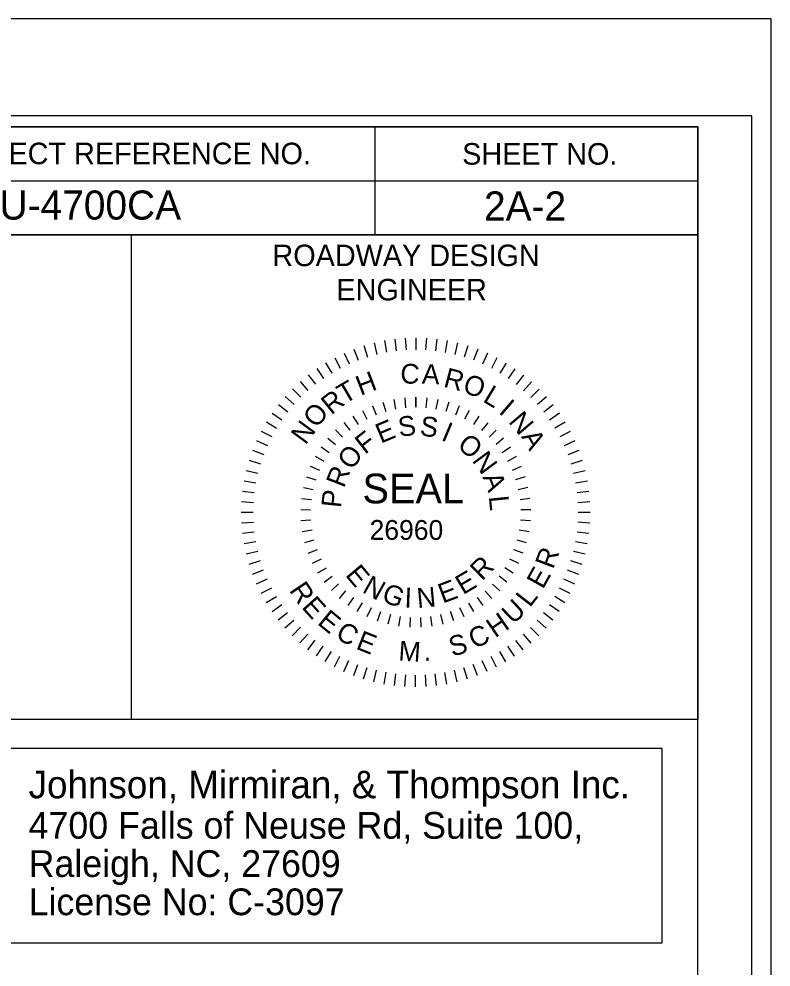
# Model space of a CAD drawing. Extents: x 2294370 to 2294957, y 719276 to 719941.
# Drawn here: x 2294757.04 to 2294791.96, y 719452.35 to 719496.34 of the extents above; entities that cross this region are included whole.
import ezdxf

# ---------------------------------------------------------------- set-up
doc = ezdxf.new("R2010")
doc.units = 0
for name, color, linetype in [('Default', 7, 'Continuous'), ('Old_Level_11', 7, 'Continuous'), ('Sheet Cutting Line CELL', 7, 'Continuous'), ('Sheet Data Field CELL', 7, 'Continuous'), ('Sheet Plan CELL', 7, 'Continuous'), ('Sheet Plot Border Inside CELL', 7, 'Continuous'), ('Sheet Plot Border Outside CELL', 7, 'Continuous'), ('Sheet Typical CELL', 7, 'Continuous')]:
    doc.layers.add(name, color=color, linetype=linetype)

msp = doc.modelspace()

# ---------------------------------------------------------------- linework, layer by layer
at = {"layer": 'Default'}
for p, q in [((2294774.009, 719481.414), (2294774.108, 719480.871)), ((2294774.493, 719481.487), (2294774.559, 719480.939)), ((2294774.98, 719481.531), (2294775.013, 719480.98)), ((2294775.47, 719481.545), (2294775.469, 719480.993)), ((2294775.959, 719481.53), (2294775.925, 719480.979)), ((2294776.446, 719481.485), (2294776.379, 719480.937)), ((2294776.93, 719481.412), (2294776.83, 719480.869)), ((2294772.597, 719481.022), (2294772.793, 719480.505)), ((2294773.059, 719481.181), (2294773.223, 719480.653)), ((2294773.531, 719481.312), (2294773.662, 719480.776)), ((2294777.407, 719481.308), (2294777.276, 719480.772)), ((2294777.88, 719481.177), (2294777.715, 719480.649)), ((2294778.341, 719481.017), (2294778.145, 719480.5)), ((2294771.705, 719480.621), (2294771.961, 719480.132)), ((2294772.145, 719480.834), (2294772.37, 719480.331)), ((2294778.793, 719480.828), (2294778.567, 719480.325)), ((2294779.233, 719480.614), (2294778.976, 719480.125)), ((2294770.867, 719480.116), (2294771.18, 719479.661)), ((2294771.278, 719480.381), (2294771.564, 719479.908)), ((2294779.659, 719480.373), (2294779.373, 719479.901)), ((2294780.07, 719480.107), (2294779.756, 719479.653)), ((2294770.473, 719479.826), (2294770.813, 719479.391)), ((2294780.463, 719479.817), (2294780.123, 719479.383)), ((2294770.096, 719479.513), (2294770.462, 719479.1)), ((2294780.839, 719479.503), (2294780.473, 719479.09)), ((2294769.404, 719478.822), (2294769.817, 719478.456)), ((2294769.74, 719479.178), (2294770.13, 719478.787)), ((2294774.951, 719478.759), (2294774.996, 719478.302)), ((2294775.467, 719478.784), (2294775.467, 719478.324)), ((2294775.467, 719478.324), (2294775.467, 719478.784)), ((2294775.983, 719478.758), (2294775.938, 719478.301)), ((2294781.195, 719479.167), (2294780.804, 719478.778)), ((2294781.53, 719478.811), (2294781.117, 719478.445)), ((2294769.09, 719478.446), (2294769.525, 719478.106)), ((2294773.453, 719478.392), (2294773.626, 719477.965)), ((2294773.941, 719478.563), (2294774.071, 719478.121)), ((2294774.441, 719478.685), (2294774.529, 719478.233)), ((2294776.492, 719478.683), (2294776.404, 719478.232)), ((2294776.993, 719478.56), (2294776.862, 719478.118)), ((2294777.48, 719478.388), (2294777.306, 719477.962)), ((2294781.843, 719478.434), (2294781.408, 719478.095)), ((2294768.8, 719478.053), (2294769.254, 719477.739)), ((2294772.54, 719477.914), (2294772.792, 719477.528)), ((2294772.986, 719478.174), (2294773.198, 719477.767)), ((2294777.947, 719478.17), (2294777.734, 719477.763)), ((2294778.392, 719477.908), (2294778.14, 719477.523)), ((2294782.133, 719478.041), (2294781.678, 719477.727)), ((2294768.534, 719477.642), (2294769.006, 719477.356)), ((2294772.123, 719477.611), (2294772.411, 719477.251)), ((2294778.809, 719477.604), (2294778.52, 719477.245)), ((2294782.398, 719477.63), (2294781.925, 719477.344)), ((2294768.293, 719477.216), (2294768.782, 719476.959)), ((2294771.737, 719477.269), (2294772.058, 719476.939)), ((2294779.195, 719477.262), (2294778.873, 719476.933)), ((2294782.638, 719477.203), (2294782.149, 719476.947)), ((2294768.079, 719476.776), (2294768.582, 719476.55)), ((2294771.385, 719476.892), (2294771.736, 719476.595)), ((2294779.546, 719476.884), (2294779.194, 719476.588)), ((2294782.851, 719476.762), (2294782.348, 719476.537)), ((2294767.891, 719476.324), (2294768.407, 719476.128)), ((2294771.071, 719476.482), (2294771.449, 719476.22)), ((2294779.859, 719476.474), (2294779.48, 719476.212)), ((2294783.039, 719476.31), (2294782.522, 719476.115)), ((2294767.731, 719475.863), (2294768.259, 719475.698)), ((2294770.799, 719476.045), (2294771.2, 719475.819)), ((2294780.13, 719476.036), (2294779.728, 719475.812)), ((2294783.198, 719475.848), (2294782.67, 719475.685)), ((2294767.599, 719475.39), (2294768.135, 719475.259)), ((2294770.569, 719475.582), (2294770.991, 719475.398)), ((2294780.359, 719475.573), (2294779.937, 719475.389)), ((2294783.329, 719475.376), (2294782.793, 719475.245)), ((2294767.496, 719474.913), (2294768.039, 719474.813)), ((2294770.387, 719475.099), (2294770.824, 719474.957)), ((2294780.541, 719475.09), (2294780.103, 719474.949)), ((2294783.431, 719474.898), (2294782.888, 719474.799)), ((2294767.422, 719474.429), (2294767.97, 719474.362)), ((2294770.25, 719474.602), (2294770.7, 719474.502)), ((2294780.676, 719474.592), (2294780.227, 719474.494)), ((2294783.504, 719474.414), (2294782.956, 719474.348)), ((2294767.377, 719473.942), (2294767.928, 719473.908)), ((2294770.163, 719474.093), (2294770.619, 719474.038)), ((2294780.762, 719474.084), (2294780.306, 719474.029)), ((2294783.548, 719473.927), (2294782.997, 719473.894)), ((2294770.125, 719473.579), (2294770.585, 719473.567)), ((2294780.8, 719473.569), (2294780.34, 719473.558)), ((2294767.362, 719473.453), (2294767.914, 719473.452)), ((2294770.137, 719473.063), (2294770.596, 719473.096)), ((2294780.786, 719473.054), (2294780.328, 719473.087)), ((2294783.562, 719473.438), (2294783.01, 719473.438)), ((2294767.377, 719472.963), (2294767.927, 719472.996)), ((2294770.199, 719472.551), (2294770.652, 719472.628)), ((2294780.273, 719472.635), (2294780.727, 719472.559)), ((2294783.547, 719472.948), (2294782.996, 719472.982)), ((2294767.421, 719472.476), (2294767.968, 719472.542)), ((2294770.31, 719472.047), (2294770.753, 719472.167)), ((2294780.612, 719472.037), (2294780.169, 719472.159)), ((2294783.502, 719472.461), (2294782.954, 719472.528)), ((2294767.493, 719471.992), (2294768.036, 719472.091)), ((2294770.469, 719471.556), (2294770.899, 719471.719)), ((2294780.452, 719471.547), (2294780.022, 719471.711)), ((2294783.428, 719471.978), (2294782.886, 719472.077)), ((2294767.595, 719471.514), (2294768.132, 719471.645)), ((2294770.675, 719471.084), (2294771.087, 719471.288)), ((2294780.245, 719471.075), (2294779.834, 719471.28)), ((2294783.325, 719471.5), (2294782.789, 719471.632)), ((2294767.726, 719471.042), (2294768.254, 719471.206)), ((2294770.924, 719470.633), (2294771.316, 719470.874)), ((2294779.995, 719470.625), (2294779.604, 719470.867)), ((2294783.194, 719471.028), (2294782.666, 719471.192)), ((2294767.885, 719470.58), (2294768.402, 719470.776)), ((2294771.217, 719470.207), (2294771.583, 719470.486)), ((2294779.701, 719470.199), (2294779.335, 719470.479)), ((2294783.034, 719470.566), (2294782.517, 719470.763)), ((2294768.073, 719470.128), (2294768.576, 719470.353)), ((2294771.55, 719469.813), (2294771.886, 719470.126)), ((2294779.368, 719469.806), (2294779.032, 719470.119)), ((2294782.845, 719470.114), (2294782.342, 719470.341)), ((2294768.286, 719469.688), (2294768.776, 719469.944)), ((2294768.526, 719469.261), (2294768.999, 719469.547)), ((2294771.918, 719469.453), (2294772.224, 719469.797)), ((2294778.999, 719469.446), (2294778.694, 719469.791)), ((2294782.39, 719469.248), (2294781.918, 719469.535)), ((2294782.631, 719469.674), (2294782.142, 719469.931)), ((2294768.792, 719468.85), (2294769.246, 719469.163)), ((2294772.32, 719469.129), (2294772.591, 719469.501)), ((2294772.751, 719468.846), (2294772.985, 719469.243)), ((2294778.165, 719468.841), (2294777.931, 719469.238)), ((2294778.596, 719469.124), (2294778.326, 719469.496)), ((2294782.124, 719468.838), (2294781.67, 719469.152)), ((2294769.081, 719468.456), (2294769.516, 719468.796)), ((2294773.208, 719468.606), (2294773.403, 719469.024)), ((2294773.686, 719468.411), (2294773.839, 719468.845)), ((2294774.287, 719468.71), (2294774.176, 719468.263)), ((2294776.735, 719468.261), (2294776.625, 719468.708)), ((2294777.229, 719468.407), (2294777.076, 719468.842)), ((2294777.707, 719468.602), (2294777.514, 719469.02)), ((2294781.834, 719468.444), (2294781.4, 719468.785)), ((2294769.394, 719468.079), (2294769.808, 719468.445)), ((2294774.686, 719468.163), (2294774.753, 719468.618)), ((2294775.199, 719468.113), (2294775.221, 719468.572)), ((2294775.715, 719468.112), (2294775.694, 719468.572)), ((2294776.228, 719468.162), (2294776.163, 719468.617)), ((2294781.52, 719468.068), (2294781.107, 719468.435)), ((2294769.729, 719467.723), (2294770.12, 719468.113)), ((2294770.085, 719467.387), (2294770.452, 719467.8)), ((2294780.828, 719467.377), (2294780.462, 719467.791)), ((2294781.184, 719467.712), (2294780.794, 719468.103)), ((2294770.461, 719467.073), (2294770.801, 719467.508)), ((2294780.451, 719467.064), (2294780.112, 719467.499)), ((2294770.854, 719466.783), (2294771.169, 719467.237)), ((2294771.265, 719466.517), (2294771.552, 719466.989)), ((2294779.647, 719466.509), (2294779.361, 719466.982)), ((2294780.057, 719466.775), (2294779.744, 719467.229)), ((2294771.691, 719466.276), (2294771.948, 719466.765)), ((2294772.131, 719466.062), (2294772.358, 719466.565)), ((2294778.779, 719466.056), (2294778.554, 719466.559)), ((2294779.22, 719466.269), (2294778.964, 719466.759)), ((2294772.583, 719465.874), (2294772.78, 719466.39)), ((2294773.045, 719465.714), (2294773.209, 719466.242)), ((2294773.517, 719465.582), (2294773.648, 719466.118)), ((2294773.995, 719465.479), (2294774.094, 719466.022)), ((2294776.915, 719465.476), (2294776.816, 719466.019)), ((2294777.393, 719465.578), (2294777.262, 719466.115)), ((2294777.865, 719465.709), (2294777.701, 719466.237)), ((2294778.327, 719465.868), (2294778.132, 719466.385)), ((2294774.478, 719465.405), (2294774.545, 719465.953)), ((2294774.965, 719465.36), (2294774.999, 719465.911)), ((2294775.455, 719465.345), (2294775.455, 719465.897)), ((2294775.944, 719465.36), (2294775.911, 719465.911)), ((2294776.431, 719465.404), (2294776.365, 719465.951))]:
    msp.add_line(p, q, dxfattribs=at)
at = {"layer": 'Old_Level_11'}
msp.add_lwpolyline([(2294736.897, 719453.463), (2294786.907, 719453.463), (2294786.907, 719462.487), (2294736.897, 719462.487)], close=True, dxfattribs=at)
at = {"layer": 'Sheet Cutting Line CELL'}
msp.add_line((2294791.96, 719496.338), (2294455.16, 719496.338), dxfattribs=at)
at = {"layer": 'Sheet Plan CELL'}
for points in [[(2294762.275, 719463.828), (2294735.99, 719463.828), (2294735.99, 719486.328), (2294762.275, 719486.328)], [(2294788.56, 719463.828), (2294762.275, 719463.828), (2294762.275, 719486.328), (2294788.56, 719486.328)]]:
    msp.add_lwpolyline(points, dxfattribs=at)
at = {"layer": 'Sheet Plot Border Inside CELL'}
msp.add_lwpolyline([(2294791.06, 719491.848), (2294457.76, 719491.848), (2294457.76, 719280.828), (2294791.06, 719280.828)], close=True, dxfattribs=at)
at = {"layer": 'Sheet Plot Border Outside CELL'}
for points in [[(2294455.16, 719276.338), (2294791.96, 719276.338), (2294791.96, 719496.338), (2294455.16, 719496.338)], [(2294791.96, 719496.338), (2294455.16, 719496.338), (2294455.16, 719276.338), (2294791.96, 719276.338)]]:
    msp.add_lwpolyline(points, close=True, dxfattribs=at)
at = {"layer": 'Sheet Typical CELL'}
for p, q in [((2294773.56, 719491.328), (2294773.56, 719486.328)), ((2294748.55, 719488.828), (2294788.56, 719488.828))]:
    msp.add_line(p, q, dxfattribs=at)
for points in [[(2294788.56, 719491.338), (2294488.56, 719491.338), (2294488.56, 719281.338), (2294788.56, 719281.338)], [(2294748.55, 719491.338), (2294788.56, 719491.338), (2294788.56, 719486.328), (2294748.55, 719486.328)], [(2294788.56, 719486.328), (2294788.56, 719486.328), (2294788.56, 719463.828), (2294788.56, 719463.828)]]:
    msp.add_lwpolyline(points, close=True, dxfattribs=at)

# ---------------------------------------------------------------- texts
at = {"layer": 'Default'}
for s, height, rotation, p in [('C', 0.919, 357.3039, (2294774.732, 719479.438)), ('A', 0.919, 357.3039, (2294775.737, 719479.419)), ('R', 0.919, 345.2946, (2294776.711, 719479.282)), ('H', 0.919, 21.0146, (2294772.902, 719478.849)), ('O', 0.919, 342.2378, (2294777.601, 719479.017)), ('T', 0.919, 30.4466, (2294772.161, 719478.449)), ('L', 0.919, 329.1015, (2294778.536, 719478.606)), ('R', 0.919, 38.6075, (2294771.542, 719477.935)), ('O', 0.919, 51.6643, (2294770.876, 719477.316)), ('I', 0.919, 319.5261, (2294779.277, 719478.072)), ('S', 0.919, 7.5951, (2294774.707, 719476.942)), ('S', 0.919, 352.2989, (2294775.625, 719477.018)), ('N', 0.919, 310.2316, (2294779.738, 719477.638)), ('N', 0.919, 53.6237, (2294770.347, 719476.54)), ('E', 0.919, 22.8914, (2294773.843, 719476.627)), ('I', 0.919, 337.0026, (2294776.603, 719476.818)), ('F', 0.919, 38.1876, (2294773.107, 719476.107)), ('O', 0.919, 321.7064, (2294777.344, 719476.459)), ('A', 0.919, 300.4641, (2294780.344, 719476.958)), ('O', 0.919, 53.4838, (2294772.495, 719475.367)), ('N', 0.919, 306.4101, (2294778.051, 719475.843)), ('R', 0.919, 68.7801, (2294772.13, 719474.541)), ('SEAL', 1.3802, 359.947, (2294772.99, 719473.862)), ('A', 0.919, 291.1139, (2294778.555, 719475.089)), ('P', 0.919, 84.0763, (2294771.99, 719473.63)), ('L', 0.919, 275.8176, (2294778.852, 719474.179)), ('26960', 0.9194, 359.947, (2294773.322, 719472.17)), ('R', 0.919, 69.6194, (2294781.842, 719470.774)), ('R', 0.919, 44.5119, (2294778.539, 719470.238)), ('E', 0.919, 310.0171, (2294772.164, 719470.528)), ('E', 0.919, 60.9466, (2294781.368, 719469.846)), ('N', 0.919, 330.8721, (2294772.936, 719469.761)), ('E', 0.919, 30.7408, (2294777.662, 719469.598)), ('R', 0.919, 303.882, (2294769.566, 719469.827)), ('G', 0.919, 339.6384, (2294773.835, 719469.329)), ('I', 0.919, 357.7332, (2294774.93, 719469.034)), ('N', 0.919, 5.3628, (2294775.554, 719469.002)), ('E', 0.919, 20.7549, (2294776.719, 719469.206)), ('E', 0.919, 311.9538, (2294770.135, 719469.033)), ('L', 0.919, 52.154, (2294780.759, 719469)), ('U', 0.919, 43.2714, (2294779.988, 719468.215)), ('E', 0.919, 320.5966, (2294770.859, 719468.282)), ('H', 0.919, 34.3888, (2294779.15, 719467.595)), ('C', 0.919, 329.2691, (2294771.687, 719467.649)), ('C', 0.919, 25.5662, (2294778.19, 719467.089)), ('E', 0.919, 338.2416, (2294772.641, 719467.13)), ('S', 0.919, 16.5636, (2294777.161, 719466.741)), ('M', 0.919, 356.0369, (2294774.644, 719466.574)), ('.', 0.919, 3.7793, (2294775.845, 719466.545))]:
    msp.add_text(s, height=height, rotation=rotation, dxfattribs=at).set_placement(p)
at = {"layer": 'Old_Level_11'}
for s, height, p in [('Johnson, Mirmiran, & Thompson Inc.', 1.2778, (2294757.492, 719460.176)), ('4700 Falls of Neuse Rd, Suite 100, ', 1.24129, (2294757.492, 719458.301)), ('Raleigh, NC, 27609', 1.24129, (2294757.492, 719456.527)), ('License No: C-3097', 1.24129, (2294757.492, 719454.753))]:
    msp.add_text(s, height=height, dxfattribs=at).set_placement(p)
at = {"layer": 'Sheet Data Field CELL'}
msp.add_text('U-4700CA', height=1.35, rotation=360, dxfattribs=at).set_placement((2294756.142, 719487.029))
msp.add_text('2A-2', height=1.35, dxfattribs=at).set_placement((2294778.634, 719486.986))
at = {"layer": 'Sheet Plan CELL'}
for s, height, p in [('ROADWAY DESIGN', 1.00002, (2294768.812, 719484.868)), ('ENGINEER', 1, (2294771.782, 719483.278))]:
    msp.add_text(s, height=height, dxfattribs=at).set_placement(p)
at = {"layer": 'Sheet Typical CELL'}
for s, height, p in [('PROJECT REFERENCE NO.', 1.00002, (2294752.99, 719489.598)), ('SHEET NO.', 1, (2294777.62, 719489.578))]:
    msp.add_text(s, height=height, dxfattribs=at).set_placement(p)

doc.saveas('drawing.dxf')
